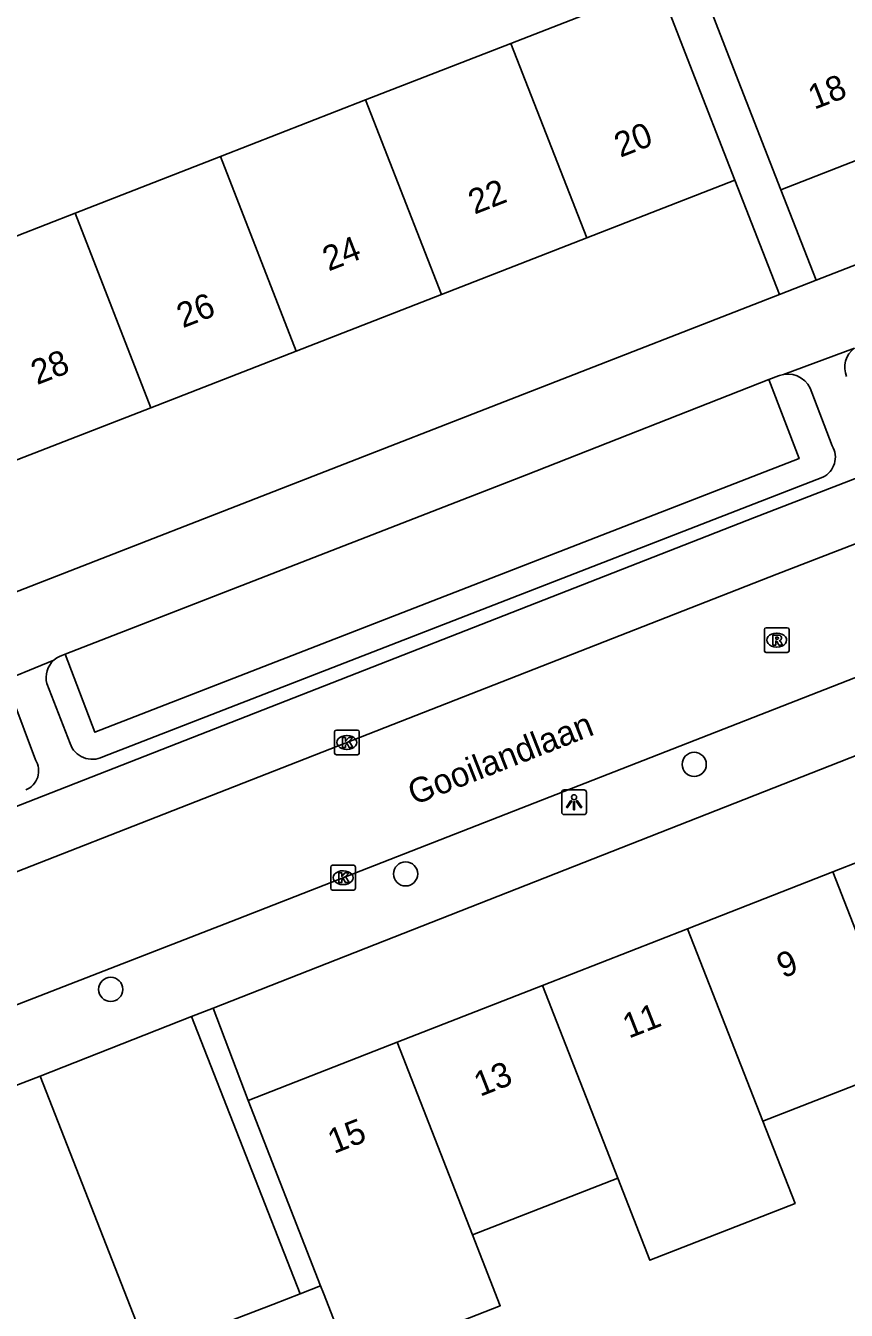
# Model space of a CAD drawing. Extents: x 159689 to 160786, y 387323 to 388339.
# Drawn here: x 160126.1 to 160159.3, y 387604.9 to 387656.8 of the extents above; entities that cross this region are included whole.
import ezdxf

# ---------------------------------------------------------------- set-up
doc = ezdxf.new("R2010")
doc.units = 0
for name, color, linetype in [('IMGEO_Boom', 7, 'Continuous'), ('IMGEO_Groenvoorziening', 7, 'Continuous'), ('IMGEO_Kolk', 7, 'Continuous'), ('IMGEO_Lichtpunt', 7, 'Continuous'), ('IMGEO_Openbare_ruimte_label', 7, 'Continuous'), ('IMGEO_Pand', 7, 'Continuous'), ('IMGEO_Pand_nummerreeks', 7, 'Continuous'), ('IMGEO_Parkeervlak_open', 7, 'Continuous'), ('IMGEO_Rijbaan_lokaal_open', 7, 'Continuous'), ('IMGEO_Rioolput', 7, 'Continuous'), ('IMGEO_Voetpad_open', 7, 'Continuous')]:
    doc.layers.add(name, color=color, linetype=linetype)

msp = doc.modelspace()

# ---------------------------------------------------------------- linework, layer by layer
at = {"layer": 'IMGEO_Boom'}
for centre in [(160153.151, 387626.929), (160141.488, 387622.502), (160129.573, 387617.833)]:
    msp.add_circle(centre, 0.489, dxfattribs=at)
at = {"layer": 'IMGEO_Groenvoorziening'}
msp.add_lwpolyline([(160156.173, 387642.481), (160157.389, 387639.292), (160128.934, 387628.231), (160127.731, 387631.387)], dxfattribs=at)
at = {"layer": 'IMGEO_Kolk'}
for p, q in [((160138.614, 387627.389), (160138.614, 387628.241)), ((160138.689, 387628.315), (160139.541, 387628.315)), ((160139.102, 387628.095), (160139.127, 387628.095)), ((160139.615, 387628.241), (160139.615, 387627.389)), ((160139.125, 387627.535), (160139.1, 387627.535)), ((160139.541, 387627.315), (160138.689, 387627.315)), ((160138.463, 387621.923), (160138.463, 387622.775)), ((160138.538, 387622.849), (160139.39, 387622.849)), ((160139.464, 387622.775), (160139.464, 387621.923)), ((160138.951, 387622.629), (160138.976, 387622.629)), ((160139.39, 387621.849), (160138.538, 387621.849)), ((160138.974, 387622.069), (160138.949, 387622.069))]:
    msp.add_line(p, q, dxfattribs=at)
for points in [[(160138.614, 387627.389), (160138.614, 387628.241)], [(160138.689, 387628.315), (160139.541, 387628.315)], [(160138.935, 387628.015), (160139.058, 387628.015), (160139.058, 387627.864), (160139.188, 387628.015), (160139.352, 387628.015), (160139.206, 387627.864), (160139.359, 387627.615), (160139.207, 387627.615), (160139.122, 387627.779), (160139.058, 387627.712), (160139.058, 387627.615), (160138.935, 387627.615), (160138.935, 387628.015)], [(160139.615, 387628.241), (160139.615, 387627.389)], [(160139.541, 387627.315), (160138.689, 387627.315)], [(160138.463, 387621.923), (160138.463, 387622.775)], [(160138.538, 387622.849), (160139.39, 387622.849)], [(160139.464, 387622.775), (160139.464, 387621.923)], [(160138.784, 387622.549), (160138.907, 387622.549), (160138.907, 387622.398), (160139.037, 387622.549), (160139.201, 387622.549), (160139.055, 387622.398), (160139.208, 387622.149), (160139.056, 387622.149), (160138.971, 387622.313), (160138.907, 387622.246), (160138.907, 387622.149), (160138.784, 387622.149), (160138.784, 387622.549)], [(160139.39, 387621.849), (160138.538, 387621.849)]]:
    msp.add_lwpolyline(points, dxfattribs=at)
for centre, start, end in [((160138.691, 387628.239), 91.552, 178.448), ((160138.691, 387628.239), 91.552, 178.448), ((160139.539, 387628.239), 1.552, 88.448), ((160139.539, 387628.239), 1.552, 88.448), ((160138.691, 387627.391), 181.552, 268.448), ((160138.691, 387627.391), 181.552, 268.448), ((160139.539, 387627.391), 271.552, 358.448), ((160139.539, 387627.391), 271.552, 358.448), ((160138.54, 387622.773), 91.552, 178.448), ((160138.54, 387622.773), 91.552, 178.448), ((160139.388, 387622.773), 1.552, 88.448), ((160139.388, 387622.773), 1.552, 88.448), ((160138.54, 387621.925), 181.552, 268.448), ((160138.54, 387621.925), 181.552, 268.448), ((160139.388, 387621.925), 271.552, 358.448), ((160139.388, 387621.925), 271.552, 358.448)]:
    msp.add_arc(centre, 0.0765, start, end, dxfattribs=at)
for centre, major_axis, ratio, start_param, end_param in [((160139.101, 387627.815), (-0.387, 0.002), 0.722429, 4.712389, 7.853982), ((160139.126, 387627.815), (-0.39, 0.002), 0.717154, 1.570796, 4.712389), ((160138.95, 387622.349), (-0.387, 0.002), 0.722429, 4.712389, 7.853982), ((160138.975, 387622.349), (-0.39, 0.002), 0.717154, 1.570796, 4.712389)]:
    msp.add_ellipse(centre, major_axis=major_axis, ratio=ratio, start_param=start_param, end_param=end_param, dxfattribs=at)
at = {"layer": 'IMGEO_Lichtpunt'}
for p, q in [((160148.699, 387625.897), (160147.891, 387625.897)), ((160148.699, 387625.897), (160147.891, 387625.897)), ((160147.797, 387625.802), (160147.797, 387624.995)), ((160147.797, 387625.802), (160147.797, 387624.995)), ((160148.793, 387624.995), (160148.793, 387625.802)), ((160148.793, 387624.995), (160148.793, 387625.802)), ((160147.891, 387624.901), (160148.699, 387624.901)), ((160147.891, 387624.901), (160148.699, 387624.901))]:
    msp.add_line(p, q, dxfattribs=at)
for points in [[(160148.171, 387625.466), (160148.21, 387625.438), (160148.022, 387625.176), (160147.984, 387625.203), (160148.171, 387625.466)], [(160148.273, 387625.418), (160148.32, 387625.418), (160148.32, 387625.096), (160148.273, 387625.096), (160148.273, 387625.418)], [(160148.383, 387625.438), (160148.421, 387625.465), (160148.608, 387625.203), (160148.569, 387625.175), (160148.383, 387625.438)]]:
    msp.add_lwpolyline(points, dxfattribs=at)
msp.add_circle((160148.296, 387625.6), 0.0994, dxfattribs=at)
for centre, start, end in [((160147.891, 387625.802), 90, 180), ((160147.891, 387625.802), 90, 180), ((160148.699, 387625.802), 0, 90), ((160148.699, 387625.802), 0, 90), ((160147.891, 387624.995), 180, 270), ((160147.891, 387624.995), 180, 270), ((160148.699, 387624.995), 270, 0), ((160148.699, 387624.995), 270, 360)]:
    msp.add_arc(centre, 0.0946, start, end, dxfattribs=at)
at = {"layer": 'IMGEO_Pand'}
for points in [[(160145.743, 387656.076), (160151.731, 387658.411)], [(160151.731, 387658.411), (160152.98, 387655.208), (160154.796, 387650.549)], [(160156.654, 387650.157), (160154.839, 387654.816), (160153.588, 387658.027)], [(160139.873, 387653.787), (160145.743, 387656.076)], [(160145.743, 387656.076), (160148.808, 387648.214)], [(160134.003, 387651.498), (160139.873, 387653.787)], [(160142.938, 387645.925), (160139.873, 387653.787)], [(160162.623, 387652.482), (160156.654, 387650.157)], [(160128.133, 387649.209), (160134.003, 387651.498)], [(160134.003, 387651.498), (160137.069, 387643.637)], [(160148.808, 387648.214), (160154.796, 387650.549)], [(160122.265, 387646.921), (160128.133, 387649.209)], [(160131.199, 387641.348), (160128.133, 387649.209)], [(160142.938, 387645.925), (160148.808, 387648.214)], [(160137.069, 387643.637), (160142.938, 387645.925)], [(160137.069, 387643.637), (160131.199, 387641.348)], [(160125.33, 387639.06), (160131.199, 387641.348)], [(160164.617, 387624.877), (160158.75, 387622.583)], [(160158.75, 387622.583), (160152.882, 387620.288)], [(160158.75, 387622.583), (160161.794, 387614.799)], [(160152.882, 387620.288), (160147.015, 387617.993)], [(160152.882, 387620.288), (160155.927, 387612.501)], [(160147.015, 387617.993), (160141.147, 387615.699)], [(160150.061, 387610.203), (160147.015, 387617.993)], [(160141.147, 387615.699), (160135.126, 387613.344)], [(160144.194, 387607.906), (160141.147, 387615.699)], [(160155.927, 387612.501), (160161.794, 387614.799)], [(160138.055, 387605.844), (160135.126, 387613.344)], [(160150.061, 387610.203), (160151.36, 387606.882), (160157.226, 387609.18), (160155.927, 387612.501)], [(160144.194, 387607.906), (160150.061, 387610.203)], [(160139.288, 387602.69), (160145.313, 387605.047), (160144.194, 387607.906)], [(160138.055, 387605.844), (160138.171, 387605.547), (160139.288, 387602.69)]]:
    msp.add_lwpolyline(points, dxfattribs=at)
at = {"layer": 'IMGEO_Parkeervlak_open'}
msp.add_lwpolyline([(160137.223, 387605.524), (160136.118, 387605.099), (160132.433, 387603.683)], dxfattribs=at)
at = {"layer": 'IMGEO_Rijbaan_lokaal_open'}
for points in [[(160101.294, 387613.006), (160156.486, 387634.615), (160204.886, 387653.326), (160214.931, 387657.325)], [(160186.627, 387640.98), (160134.686, 387620.678), (160125.563, 387617.123)], [(160126.718, 387614.332), (160121.589, 387612.364)], [(160132.433, 387603.683), (160131.091, 387603.167), (160126.718, 387614.332)]]:
    msp.add_lwpolyline(points, dxfattribs=at)
at = {"layer": 'IMGEO_Rioolput'}
for p, q in [((160155.985, 387631.526), (160155.985, 387632.378)), ((160156.06, 387632.452), (160156.912, 387632.452)), ((160156.473, 387632.232), (160156.498, 387632.232)), ((160156.986, 387632.378), (160156.986, 387631.526)), ((160156.496, 387631.672), (160156.471, 387631.672)), ((160156.912, 387631.452), (160156.06, 387631.452))]:
    msp.add_line(p, q, dxfattribs=at)
for points in [[(160155.985, 387631.526), (160155.985, 387632.378)], [(160156.06, 387632.452), (160156.912, 387632.452)], [(160156.574, 387632.15), (160156.322, 387632.152), (160156.322, 387631.752)], [(160156.986, 387632.378), (160156.986, 387631.526)], [(160156.322, 387631.752), (160156.446, 387631.752), (160156.446, 387631.914), (160156.457, 387631.914)], [(160156.5, 387632.071), (160156.446, 387632.071), (160156.446, 387631.99)], [(160156.446, 387631.99), (160156.498, 387631.99)], [(160156.504, 387631.885), (160156.575, 387631.752), (160156.715, 387631.752), (160156.65, 387631.878)], [(160156.912, 387631.452), (160156.06, 387631.452)]]:
    msp.add_lwpolyline(points, dxfattribs=at)
for centre, radius, start, end in [((160156.062, 387632.376), 0.0765, 91.552, 178.448), ((160156.062, 387632.376), 0.0765, 91.552, 178.448), ((160156.573, 387632.04), 0.109, 350.3612, 89.416), ((160156.91, 387632.376), 0.0765, 1.552, 88.448), ((160156.91, 387632.376), 0.0765, 1.552, 88.448), ((160156.456, 387631.861), 0.0533, 26.0293, 88.6989), ((160156.482, 387632.179), 0.19, 274.7715, 282.9687), ((160156.506, 387631.975), 0.0964, 77.0061, 93.1865), ((160156.52, 387632.032), 0.0378, 276.6634, 79.6772), ((160156.571, 387632.04), 0.112, 277.5842, 350.9817), ((160156.555, 387631.825), 0.108, 29.5134, 73.7905), ((160156.062, 387631.528), 0.0765, 181.552, 268.448), ((160156.062, 387631.528), 0.0765, 181.552, 268.448), ((160156.91, 387631.528), 0.0765, 271.552, 358.448), ((160156.91, 387631.528), 0.0765, 271.552, 358.448)]:
    msp.add_arc(centre, radius, start, end, dxfattribs=at)
for centre, major_axis, ratio, start_param, end_param in [((160156.472, 387631.952), (-0.387, 0.002), 0.722429, 4.712389, 7.853982), ((160156.497, 387631.952), (-0.39, 0.002), 0.717154, 1.570796, 4.712389)]:
    msp.add_ellipse(centre, major_axis=major_axis, ratio=ratio, start_param=start_param, end_param=end_param, dxfattribs=at)
at = {"layer": 'IMGEO_Voetpad_open'}
for points in [[(160211.11, 387667.165), (160158.078, 387646.502)], [(160210.973, 387658.364), (160203.991, 387655.625), (160155.591, 387636.914), (160103.815, 387616.643)], [(160154.796, 387650.549), (160156.598, 387645.925)], [(160158.078, 387646.502), (160156.654, 387650.157)], [(160156.598, 387645.925), (160158.078, 387646.502)], [(160156.598, 387645.925), (160097.659, 387622.96)], [(160156.765, 387642.691), (160159.626, 387643.752)], [(160127.731, 387631.387), (160146.377, 387638.629), (160156.173, 387642.481)], [(160156.173, 387642.481), (160156.553, 387642.63)], [(160158.728, 387639.803), (160157.905, 387641.959)], [(160129.254, 387627.23), (160158.348, 387638.541)], [(160133.717, 387617.078), (160180.916, 387635.628), (160182.376, 387631.822)], [(160124.771, 387630.123), (160127.276, 387631.147)], [(160127.59, 387631.331), (160127.731, 387631.387)], [(160126.994, 387630.195), (160127.927, 387627.77)], [(160126.526, 387627.113), (160125.571, 387629.667)], [(160133.717, 387617.078), (160132.833, 387616.731)], [(160135.126, 387613.344), (160133.717, 387617.078)], [(160132.833, 387616.731), (160126.718, 387614.332)], [(160132.833, 387616.731), (160137.223, 387605.524)], [(160137.223, 387605.524), (160138.055, 387605.844)]]:
    msp.add_lwpolyline(points, dxfattribs=at)
for centre, radius, start, end in [((160160.193, 387642.979), 0.958, 126.2815, 202.8614), ((160156.946, 387641.662), 1.045, 99.9923, 112.1126), ((160156.933, 387641.699), 1.006, 14.9637, 99.6268), ((160157.967, 387639.344), 0.889, 295.3979, 31.087), ((160127.901, 387630.444), 0.94, 131.6327, 195.3668), ((160127.907, 387630.43), 0.955, 109.3883, 131.3512), ((160128.834, 387628.099), 0.965, 199.9434, 295.7705), ((160125.839, 387626.666), 0.82, 291.1057, 33.0486)]:
    msp.add_arc(centre, radius, start, end, dxfattribs=at)

# ---------------------------------------------------------------- texts
at = {"layer": 'IMGEO_Openbare_ruimte_label'}
msp.add_text('Gooilandlaan', height=1, rotation=21.4077, dxfattribs=at).set_placement((160141.829, 387625.27))
at = {"layer": 'IMGEO_Pand_nummerreeks'}
for s, rotation, p in [('18', 21.2834, (160158.004, 387653.387)), ('20', 21.3017, (160150.167, 387651.449)), ('22', 21.3017, (160144.269, 387649.149)), ('24', 21.3017, (160138.377, 387646.852)), ('26', 21.3017, (160132.484, 387644.554)), ('28', 21.3017, (160126.594, 387642.257)), ('9', 21.3589, (160156.736, 387618.273)), ('11', 21.3599, (160150.508, 387615.838)), ('13', 21.3589, (160144.496, 387613.487)), ('15', 21.3599, (160138.589, 387611.177))]:
    msp.add_text(s, height=1, rotation=rotation, dxfattribs=at).set_placement(p)

doc.saveas('drawing.dxf')
